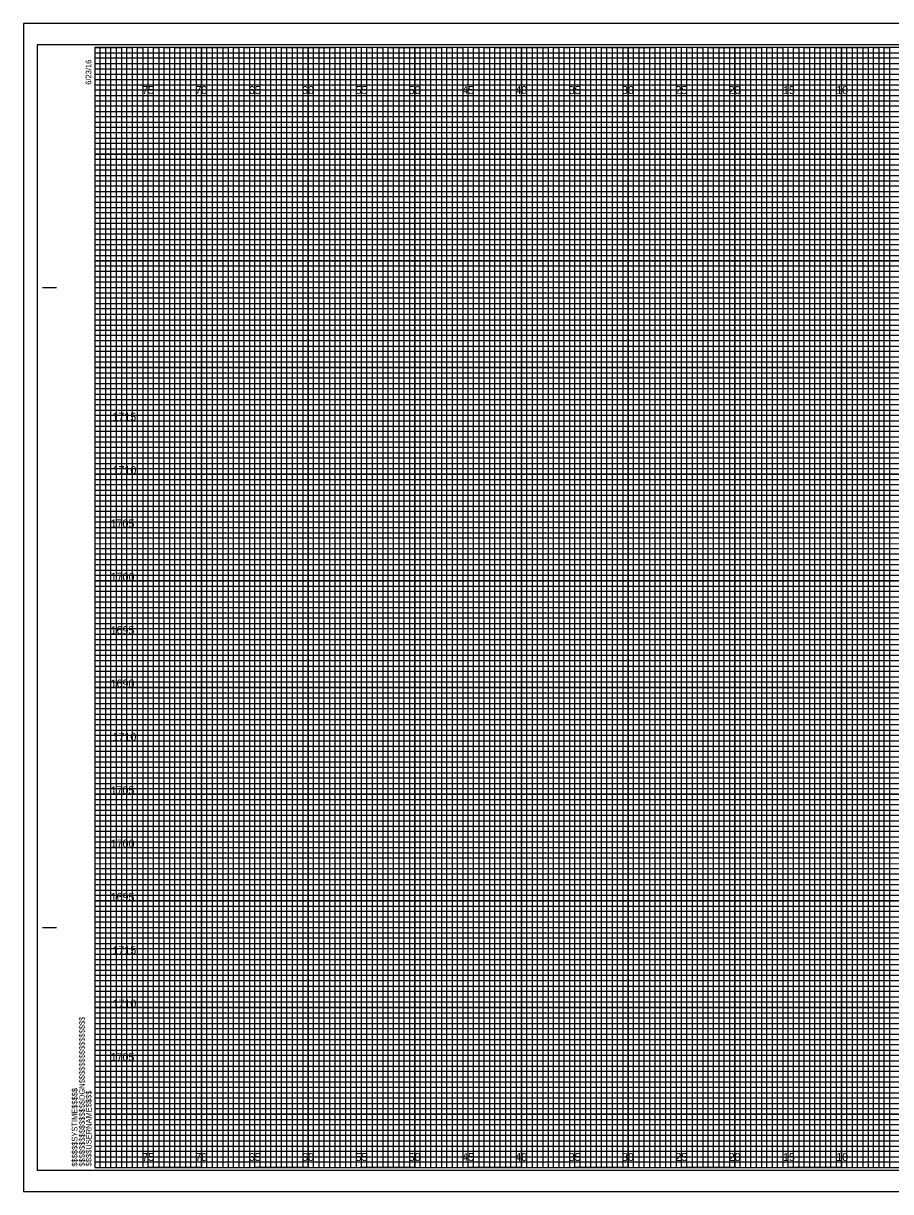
# Model space of a CAD drawing. Extents: x -7 to 162, y -2 to 107.
# Drawn here: x -6.7 to 74.6, y -2.3 to 107.3 of the extents above; entities that cross this region are included whole.
import ezdxf

# ---------------------------------------------------------------- set-up
doc = ezdxf.new("R2010")
doc.units = 0
for name, color, linetype in [('Prop XS Elevation Labels', 7, 'Continuous'), ('Prop XS Offset Labels', 7, 'Continuous'), ('Sheet Cross Section CELL', 7, 'Continuous'), ('Sheet Cross Section Grid Major CELL', 7, 'Continuous'), ('Sheet Cross Section Grid Middle CELL', 7, 'Continuous'), ('Sheet Cross Section Grid Minor 1 CELL', 7, 'Continuous'), ('Sheet Cross Section Grid Minor 2 CELL', 7, 'Continuous'), ('Sheet Cutting Line CELL', 7, 'Continuous'), ('Sheet DOT Grid CELL', 7, 'Continuous'), ('Sheet Plot Border Inside CELL', 7, 'Continuous'), ('Sheet Plot Border Outside CELL', 7, 'Continuous')]:
    doc.layers.add(name, color=color, linetype=linetype)

msp = doc.modelspace()

# ---------------------------------------------------------------- linework, layer by layer
at = {"layer": 'Sheet Cross Section CELL'}
for p, q in [((-4.9, 82.5), (-3.65, 82.5)), ((-4.85, 82.5), (-3.6, 82.5)), ((-4.9, 22.5), (-3.65, 22.5)), ((-4.85, 22.5), (-3.6, 22.5)), ((0, 0), (0, 0)), ((0, 0), (0, 0)), ((0, 0), (0, 0)), ((0, 0), (0, 0)), ((0, 0), (0, 0)), ((0, 0), (0, 0)), ((0, 0), (0, 0))]:
    msp.add_line(p, q, dxfattribs=at)
msp.add_lwpolyline([(160, 105), (0, 105), (0, 0), (160, 0)], close=True, dxfattribs=at)
at = {"layer": 'Sheet Cross Section Grid Major CELL'}
for p, q in [((5, 105), (0, 105)), ((5, 0), (5, 105)), ((15, 105), (10, 105)), ((10, 105), (10, 0)), ((15, 0), (15, 105)), ((25, 105), (20, 105)), ((20, 105), (20, 0)), ((25, 0), (25, 105)), ((35, 105), (30, 105)), ((30, 105), (30, 0)), ((35, 0), (35, 105)), ((45, 105), (40, 105)), ((40, 105), (40, 0)), ((45, 0), (45, 105)), ((55, 105), (50, 105)), ((50, 105), (50, 0)), ((55, 0), (55, 105)), ((65, 105), (60, 105)), ((60, 105), (60, 0)), ((65, 0), (65, 105)), ((75, 105), (70, 105)), ((70, 105), (70, 0)), ((10, 0), (5, 0)), ((20, 0), (15, 0)), ((30, 0), (25, 0)), ((40, 0), (35, 0)), ((50, 0), (45, 0)), ((60, 0), (55, 0)), ((70, 0), (65, 0))]:
    msp.add_line(p, q, dxfattribs=at)
for points in [[(0, 100), (160, 100), (160, 95), (0, 95)], [(0, 90), (160, 90), (160, 85), (0, 85)], [(0, 80), (160, 80), (160, 75), (0, 75)], [(0, 70), (160, 70), (160, 65), (0, 65)], [(0, 60), (160, 60), (160, 55), (0, 55)], [(0, 50), (160, 50), (160, 45), (0, 45)], [(0, 40), (160, 40), (160, 35), (0, 35)], [(0, 30), (160, 30), (160, 25), (0, 25)], [(0, 20), (160, 20), (160, 15), (0, 15)], [(0, 10), (160, 10), (160, 5), (0, 5)]]:
    msp.add_lwpolyline(points, dxfattribs=at)
at = {"layer": 'Sheet Cross Section Grid Middle CELL'}
for points in [[(0, 105), (2.5, 105), (2.5, 0), (7.5, 0), (7.5, 105), (12.5, 105), (12.5, 0), (17.5, 0), (17.5, 105), (22.5, 105), (22.5, 0), (27.5, 0), (27.5, 105), (32.5, 105), (32.5, 0), (37.5, 0), (37.5, 105), (42.5, 105), (42.5, 0), (47.5, 0), (47.5, 105), (52.5, 105), (52.5, 0), (57.5, 0), (57.5, 105), (62.5, 105), (62.5, 0), (67.5, 0), (67.5, 105), (72.5, 105), (72.5, 0), (77.5, 0)], [(0, 102.5), (137.5, 102.5)], [(0, 92.5), (160, 92.5), (160, 97.5), (0, 97.5)], [(0, 82.5), (160, 82.5), (160, 87.5), (0, 87.5)], [(0, 72.5), (160, 72.5), (160, 77.5), (0, 77.5)], [(0, 62.5), (160, 62.5), (160, 67.5), (0, 67.5)], [(0, 52.5), (160, 52.5), (160, 57.5), (0, 57.5)], [(0, 42.5), (160, 42.5), (160, 47.5), (0, 47.5)], [(0, 32.5), (160, 32.5), (160, 37.5), (0, 37.5)], [(0, 22.5), (160, 22.5), (160, 27.5), (0, 27.5)], [(0, 12.5), (160, 12.5), (160, 17.5), (0, 17.5)], [(0, 2.5), (160, 2.5), (160, 7.5), (0, 7.5)]]:
    msp.add_lwpolyline(points, dxfattribs=at)
at = {"layer": 'Sheet Cross Section Grid Minor 1 CELL'}
for p, q in [((0, 104.5), (130, 104.5)), ((130, 103.99), (0, 103.99)), ((0, 103.99), (0, 103.5)), ((0, 103.5), (130, 103.5)), ((130, 102.95), (0, 102.95)), ((0, 102.95), (0, 102)), ((0, 102), (160, 102))]:
    msp.add_line(p, q, dxfattribs=at)
for points in [[(0, 101.5), (135, 101.5), (160, 101.5), (160, 101), (0, 101)], [(0, 100.5), (160, 100.5), (160, 99.5), (0, 99.5)], [(0, 99), (160, 99), (160, 98.5), (0, 98.49)], [(0, 98), (160, 98), (160, 97), (0, 97)], [(0, 96.5), (160, 96.5), (160, 96), (0, 96)], [(0, 95.5), (160, 95.5), (160, 94.5), (0, 94.5)], [(0, 94), (160, 94), (160, 93.5), (0, 93.5)], [(0, 93), (160, 93), (160, 92), (0, 92)], [(0, 91.5), (160, 91.5), (160, 91), (0, 91)], [(0, 90.5), (160, 90.5), (160, 89.5), (0, 89.5)], [(0, 89), (160, 89), (160, 88.5), (0, 88.5)], [(0, 88), (160, 88), (160, 86.98), (160, 86.5), (160, 86), (0, 86)], [(0, 87), (160, 87), (160, 86.5), (0, 86.5)], [(0, 85.5), (160, 85.5), (160, 84.5), (0, 84.52)], [(0, 84.52), (160, 84.5), (160, 84), (0, 84)], [(0, 83.5), (160, 83.5), (160, 83), (0, 83)], [(0, 82), (160, 82), (160, 81.5), (0, 81.5)], [(0, 81), (160, 81), (160, 80.5), (0, 80.5)], [(-0.04, 79.45), (160, 79.45), (160, 78.94), (-0.04, 78.94)], [(0, 78.5), (160, 78.5), (160, 78), (0, 78)], [(0, 77), (160, 77), (160, 76.5), (0, 76.5)], [(0, 76), (160, 76), (160, 75.5), (0, 75.5)], [(0, 74.5), (160, 74.5), (160, 74), (0, 74)], [(0, 73.5), (160, 73.5), (160, 73), (0, 73)], [(0, 72), (160, 72), (160, 71.5), (0, 71.5)], [(0, 71), (160, 71), (160, 70.5), (0, 70.5)], [(0, 69.5), (160, 69.5), (160, 68.99), (0, 69)], [(0, 68.5), (160, 68.5), (160, 68), (0, 68)], [(0, 67), (160, 67), (160, 66.5), (0, 66.5)], [(0, 66), (160, 66), (160, 65.5), (0, 65.5)], [(0, 64.5), (160, 64.5), (160, 64), (0, 64)], [(0, 63.5), (160, 63.5), (160, 63), (0, 63)], [(0, 62), (160, 62), (160, 61.5), (0, 61.5)], [(0, 61), (160, 61), (160, 60.5), (0, 60.5)], [(0, 59.5), (160, 59.5), (160, 59), (0, 59)], [(0, 58.5), (160.03, 58.45), (160, 58), (0, 58)], [(0, 57), (160, 57), (160, 56.5), (0, 56.5)], [(0, 56), (160, 56), (160, 55.5), (0, 55.5)], [(0, 54.5), (160, 54.5), (160, 54), (0, 54)], [(0, 53.5), (160, 53.5), (160, 53), (0, 53)], [(0, 52), (160, 52), (160, 51.5), (0, 51.5)], [(0, 51), (160, 51), (160, 50.5), (0, 50.5)], [(0, 49.5), (160, 49.5), (160, 49), (0, 49)], [(0, 48.5), (160, 48.5), (160, 48), (0, 48)], [(0, 47), (160, 47), (160, 46.5), (0, 46.5)], [(0, 46), (160, 46), (160, 45.5), (0, 45.5)], [(0, 44.5), (160, 44.5), (160, 44), (0, 44)], [(0, 43.5), (160, 43.5), (160, 43), (0, 43)], [(0, 42), (160, 42), (160, 41.5), (0, 41.5)], [(0, 41), (160, 41), (160, 40.5), (0, 40.5)], [(0, 39.5), (160, 39.5), (160, 38.99), (0, 39)], [(0, 38.5), (160, 38.5), (160, 38), (0, 38)], [(0, 37), (160, 37), (160, 36.5), (0, 36.5)], [(0, 36), (160, 36), (160, 35.5), (0, 35.5)], [(0, 34.5), (160, 34.5), (160, 34), (0, 34)], [(0, 33.5), (160, 33.5), (160, 33), (0, 33)], [(0, 32), (160, 32), (160, 31.5), (0, 31.5)], [(0, 31), (160, 31), (160, 30.5), (0, 30.5)], [(0, 29.5), (160, 29.5), (160, 29), (0, 29)], [(0, 28.5), (160.03, 28.46), (160, 28), (0, 28)], [(0, 27), (160, 27), (160, 26.5), (0, 26.5)], [(0, 26), (160, 26), (160, 25.5), (0, 25.5)], [(0, 24.5), (160, 24.5), (160, 24), (0, 24)], [(0, 23.5), (160, 23.5), (160, 23), (0, 23)], [(0, 22), (160, 22), (160, 21.5), (0, 21.5)], [(0, 21), (160, 21), (160, 20.5), (0, 20.5)], [(0, 19.5), (160, 19.5), (160, 19), (0, 19)], [(0, 18.5), (160, 18.5), (160, 18), (0, 18)], [(0, 17), (160, 17), (160, 16.5), (0, 16.5)], [(0, 16), (160, 16), (160, 15.5), (0, 15.5)], [(0, 14.5), (160, 14.5), (160, 14), (0, 14)], [(0, 13.5), (160, 13.5), (160, 13), (0, 13)], [(0, 12), (160, 12), (160, 11.5), (0, 11.5)], [(0, 11), (160, 11), (160, 10.5), (0, 10.5)], [(0, 9.5), (160, 9.5), (160, 9), (0, 9)], [(0, 8.5), (160, 8.5), (160, 8), (0, 8)], [(0, 7), (160, 7), (160, 6.5), (0, 6.5)], [(0, 6), (160, 6), (160, 5.5), (0, 5.5)], [(0, 4.5), (160, 4.5), (160, 4), (0, 4)], [(0, 3.5), (160, 3.5), (160, 3), (0, 3)], [(0, 2), (160, 2), (160, 1.5), (0, 1.5)], [(0, 1), (160, 1), (160, 0.5), (0, 0.5)]]:
    msp.add_lwpolyline(points, dxfattribs=at)
at = {"layer": 'Sheet Cross Section Grid Minor 2 CELL'}
for points in [[(0, 0), (0.5, 0), (0.5, 105), (1, 105), (1, 0)], [(1, 0), (1.5, 0), (1.5, 105), (2, 105), (2, 0)], [(2.5, 0), (3, 0), (3, 105), (3.5, 105), (3.5, 0)], [(3.5, 0), (4, 0), (4, 105), (4.5, 105), (4.5, 0)], [(5, 0), (5.5, 0), (5.5, 105), (6, 105), (6, 0)], [(6, 0), (6.5, 0), (6.5, 105), (7, 105), (7, 0)], [(7.5, 0), (8, 0), (8, 105), (8.5, 105), (8.5, 0)], [(8.5, 0), (9, 0), (9, 105), (9.5, 105), (9.5, 0)], [(10, 0), (10.5, 0), (10.5, 105), (11, 105), (11, 0)], [(11, 0), (11.5, 0), (11.5, 105), (12, 105), (12, 0)], [(12.5, 0), (13, 0), (13, 105), (13.5, 105), (13.5, 0)], [(13.5, 0), (14, 0), (14, 105), (14.5, 105), (14.5, 0)], [(15, 0), (15.5, 0), (15.5, 105), (16, 105), (16, 0)], [(16, 0), (16.5, 0), (16.5, 105), (17, 105), (17, 0)], [(17.5, 0), (18, 0), (18, 105), (18.5, 105), (18.5, 0)], [(18.5, 0), (19, 0), (19, 105), (19.5, 105), (19.5, 0)], [(20, 0), (20.5, 0), (20.5, 105), (21, 105), (21, 0)], [(21, 0), (21.5, 0), (21.5, 105), (22, 105), (22, 0)], [(22.5, 0), (23, 0), (23, 105), (23.5, 105), (23.5, 0)], [(23.5, 0), (24, 0), (24, 105), (24.5, 105), (24.5, 0)], [(25, 0), (25.5, 0), (25.5, 105), (26, 105), (26, 0)], [(26, 0), (26.5, 0), (26.5, 105), (27, 105), (27, 0)], [(27.5, 0), (28, 0), (28, 105), (28.5, 105), (28.5, 0)], [(28.5, 0), (29, 0), (29, 105), (29.5, 105), (29.5, 0)], [(30, 0), (30.5, 0), (30.5, 105), (31, 105), (31, 0)], [(31, 0), (31.5, 0), (31.5, 105), (32, 105), (32, 0)], [(32.5, 0), (33, 0), (33, 105), (33.5, 105), (33.5, 0)], [(33.5, 0), (34, 0), (34, 105), (34.5, 105), (34.5, 0)], [(35, 0), (35.5, 0), (35.5, 105), (36, 105), (36, 0)], [(36, 0), (36.5, 0), (36.5, 105), (37, 105), (37, 0)], [(37.5, 0), (38, 0), (38, 105), (38.5, 105), (38.5, 0)], [(38.5, 0), (39, 0), (39, 105), (39.5, 105), (39.5, 0)], [(40, 0), (40.5, 0), (40.5, 105), (41, 105), (41, 0)], [(41, 0), (41.5, 0), (41.5, 105), (42, 105), (42, 0)], [(42.5, 0), (43, 0), (43, 105), (43.5, 105), (43.5, 0)], [(43.5, 0), (44, 0), (44, 105), (44.5, 105), (44.5, 0)], [(45, 0), (45.5, 0), (45.5, 105), (46, 105), (46, 0)], [(46, 0), (46.5, 0), (46.5, 105), (47, 105), (47, 0)], [(47.5, 0), (48, 0), (48, 105), (48.5, 105), (48.5, 0)], [(48.5, 0), (49, 0), (49, 105), (49.5, 105), (49.5, 0)], [(50, 0), (50.5, 0), (50.5, 105), (51, 105), (51, 0)], [(51, 0), (51.5, 0), (51.5, 105), (52, 105), (52, 0)], [(52.5, 0), (53, 0), (53, 105), (53.5, 105), (53.5, 0)], [(53.5, 0), (54, 0), (54, 105), (54.5, 105), (54.5, 0)], [(55, 0), (55.5, 0), (55.5, 105), (56, 105), (56, 0)], [(56, 0), (56.5, 0), (56.5, 105), (57, 105), (57, 0)], [(57.5, 0), (58, 0), (58, 105), (58.5, 105), (58.5, 0)], [(58.5, 0), (59, 0), (59, 105), (59.5, 105), (59.5, 0)], [(60, 0), (60.5, 0), (60.5, 105), (61, 105), (61, 0)], [(61, 0), (61.5, 0), (61.5, 105), (62, 105), (62, 0)], [(62.5, 0), (63, 0), (63, 105), (63.5, 105), (63.5, 0)], [(63.5, 0), (64, 0), (64, 105), (64.5, 105), (64.5, 0)], [(65, 0), (65.5, 0), (65.5, 105), (66, 105), (66, 0)], [(66, 0), (66.5, 0), (66.5, 105), (67, 105), (67, 0)], [(67.5, 0), (68, 0), (68, 105), (68.5, 105), (68.5, 0)], [(68.5, 0), (69, 0), (69, 105), (69.5, 105), (69.5, 0)], [(70, 0), (70.5, 0), (70.5, 105), (71, 105), (71, 0)], [(71, 0), (71.5, 0), (71.5, 105), (72, 105), (72, 0)], [(72.5, 0), (73, 0), (73, 105), (73.5, 105), (73.5, 0)], [(73.5, 0), (74, 0), (74, 105), (74.5, 105), (74.5, 0)]]:
    msp.add_lwpolyline(points, dxfattribs=at)
at = {"layer": 'Sheet Cutting Line CELL'}
for p, q in [((161.65, 107.25), (-6.7, 107.25)), ((-6.7, 107.25), (-6.7, -2.25)), ((-6.7, -2.25), (161.65, -2.25))]:
    msp.add_line(p, q, dxfattribs=at)
at = {"layer": 'Sheet DOT Grid CELL'}
for p, q in [((5, 0), (5, 105)), ((10, 0), (10, 105)), ((15, 0), (15, 105)), ((20, 0), (20, 105)), ((25, 0), (25, 105)), ((30, 0), (30, 105)), ((35, 0), (35, 105)), ((40, 0), (40, 105)), ((45, 0), (45, 105)), ((50, 0), (50, 105)), ((55, 0), (55, 105)), ((60, 0), (60, 105)), ((65, 0), (65, 105)), ((70, 0), (70, 105)), ((0, 100), (160, 100)), ((0, 95), (160, 95)), ((0, 90), (160, 90)), ((0, 85), (160, 85)), ((0, 80), (160, 80)), ((0, 75), (160, 75)), ((0, 70), (160, 70)), ((0, 65), (160, 65)), ((0, 60), (160, 60)), ((0, 55), (160, 55)), ((0, 50), (160, 50)), ((0, 45), (160, 45)), ((0, 40), (160, 40)), ((0, 35), (160, 35)), ((0, 30), (160, 30)), ((0, 25), (160, 25)), ((0, 20), (160, 20)), ((0, 15), (160, 15)), ((0, 10), (160, 10)), ((0, 5), (160, 5))]:
    msp.add_line(p, q, dxfattribs=at)
at = {"layer": 'Sheet Plot Border Inside CELL'}
msp.add_lwpolyline([(-5.4, -0.25), (161.2, -0.25), (161.2, 105.25), (-5.4, 105.25)], close=True, dxfattribs=at)
at = {"layer": 'Sheet Plot Border Outside CELL'}
msp.add_lwpolyline([(-6.7, -2.25), (161.65, -2.25), (161.65, 107.25), (-6.7, 107.25)], close=True, dxfattribs=at)

# ---------------------------------------------------------------- texts
at = {"layer": 'Prop XS Elevation Labels'}
for s, p in [('1715', (1.65, 70)), ('1710', (1.66, 65)), ('1705', (1.48, 60)), ('1700', (1.49, 55)), ('1695', (1.48, 50)), ('1690', (1.48, 45)), ('1710', (1.66, 40)), ('1705', (1.48, 35)), ('1700', (1.49, 30)), ('1695', (1.48, 25)), ('1715', (1.65, 20)), ('1710', (1.66, 15)), ('1705', (1.48, 10))]:
    msp.add_text(s, height=0.75, dxfattribs=at).set_placement(p)
at = {"layer": 'Prop XS Offset Labels'}
for s, p in [('75', (4.44, 100.62)), ('70', (9.43, 100.62)), ('65', (14.44, 100.62)), ('60', (19.43, 100.62)), ('55', (24.44, 100.62)), ('50', (29.43, 100.62)), ('45', (34.44, 100.62)), ('40', (39.43, 100.62)), ('35', (44.44, 100.62)), ('30', (49.43, 100.62)), ('25', (54.44, 100.62)), ('20', (59.43, 100.62)), ('15', (64.53, 100.62)), ('10', (69.52, 100.62)), ('75', (4.44, 0.62)), ('70', (9.43, 0.62)), ('65', (14.44, 0.62)), ('60', (19.43, 0.62)), ('55', (24.44, 0.62)), ('50', (29.43, 0.62)), ('45', (34.44, 0.62)), ('40', (39.43, 0.62)), ('35', (44.44, 0.62)), ('30', (49.43, 0.62)), ('25', (54.44, 0.62)), ('20', (59.43, 0.62)), ('15', (64.53, 0.62)), ('10', (69.52, 0.62))]:
    msp.add_text(s, height=0.75, dxfattribs=at).set_placement(p)
at = {"layer": 'Sheet Cross Section CELL'}
for s, p in [('6/23/16', (-0.33, 101.5)), ('$$$$$$$$$$$$$$$$DGN$$$$$$$$$$$$$$$$', (-0.94, 0.09)), ('$$$$$$SYSTIME$$$$$', (-1.63, 0.09)), ('$$$$USERNAME$$$$', (-0.31, 0.12))]:
    msp.add_text(s, height=0.525, rotation=90, dxfattribs=at).set_placement(p)

doc.saveas('drawing.dxf')
